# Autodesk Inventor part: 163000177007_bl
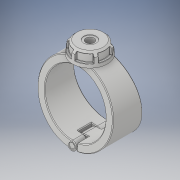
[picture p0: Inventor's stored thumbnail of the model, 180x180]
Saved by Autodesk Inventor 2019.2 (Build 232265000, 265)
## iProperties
Created: 2022-02
Part Number: 163000177007_bl
Material: Generic
Description: Plassadle Threaded 177x3/4''
Document SubType Name: Modeling
Designer: comp2
Density: 1 g/cm^3
Appearance: Default
Author: comp2
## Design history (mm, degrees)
derived "16300.ipt"
feature "Solid1::16300.ipt" dims "ScaleForDerivedMember" = 10
feature "Solid2::16300.ipt" dims "ScaleForDerivedMember" = 10
feature "Solid3::16300.ipt" dims "ScaleForDerivedMember" = 10
feature "Solid4::16300.ipt" dims "ScaleForDerivedMember" = 10
tag "TaggingFeature1"
body "Solid1"
body "Solid2"
body "Solid3"
body "Solid4"
other parameters: "d0" = 177 [user parameter], "d3" = 88.5 [user parameter], "d7" = 209 [user parameter], "d8" = 85 deg [user parameter], "d9" = 45 deg [user parameter], "d10" = 102 [user parameter], "d11" = 49 [user parameter], "d12" = 25.27 [user parameter], "d13" = 42.84 [user parameter], "d14" = 36.1755 [user parameter], "d42" = 4.3 [user parameter], "d49" = 4.4 [user parameter], "d51" = 0 [user parameter], "d52" = 30.1 [user parameter], "d53" = 121 [user parameter], "d54" = 38.5 [user parameter], "d55" = 0 [user parameter], "d56" = 22 [user parameter], "d57" = 22 [user parameter], "d59" = 0 [user parameter], "d61" = 0 [user parameter], "d62" = 38.5 [user parameter], "d63" = 0 [user parameter], "d65" = 0 [user parameter], "d67" = 0 [user parameter], "d69" = 0 [user parameter], "d70" = 1 [user parameter], "d71" = 105.6 [user parameter], "d72" = 0 [user parameter], "d73" = 2 [user parameter], "d78" = 86.7 [user parameter], "d79" = 5.1 [user parameter], "d80" = 60 deg [user parameter], "d81" = 5.1 [user parameter], "d84" = 0 [user parameter], "d85" = 1 [user parameter], "d87" = 360 deg [user parameter], "d122" = 52 [user parameter], "d124" = 42.80128 [user parameter], "d125" = 1.805 [user parameter], "d127" = 255 [user parameter], "d129" = 24.117 [user parameter], "d130" = 20.49945 [user parameter], "d131" = 33.8 [user parameter], "d132" = 45 deg [user parameter], "d133" = 23.66 [user parameter], "d134" = 12.0585 [user parameter], "d136" = 0 [user parameter], "d138" = 0 [user parameter], "d" = 177 [user parameter], "d1" = 25 [user parameter], "E_" = 54 [user parameter], "E1" = 102 [user parameter], "H1" = 255 [user parameter], "H2" = 52 [user parameter], "H3" = 78 [user parameter], "H_costum" = 49 [user parameter], "Rp" = 24.117 [user parameter], "d128" = 36.1 [user parameter]
